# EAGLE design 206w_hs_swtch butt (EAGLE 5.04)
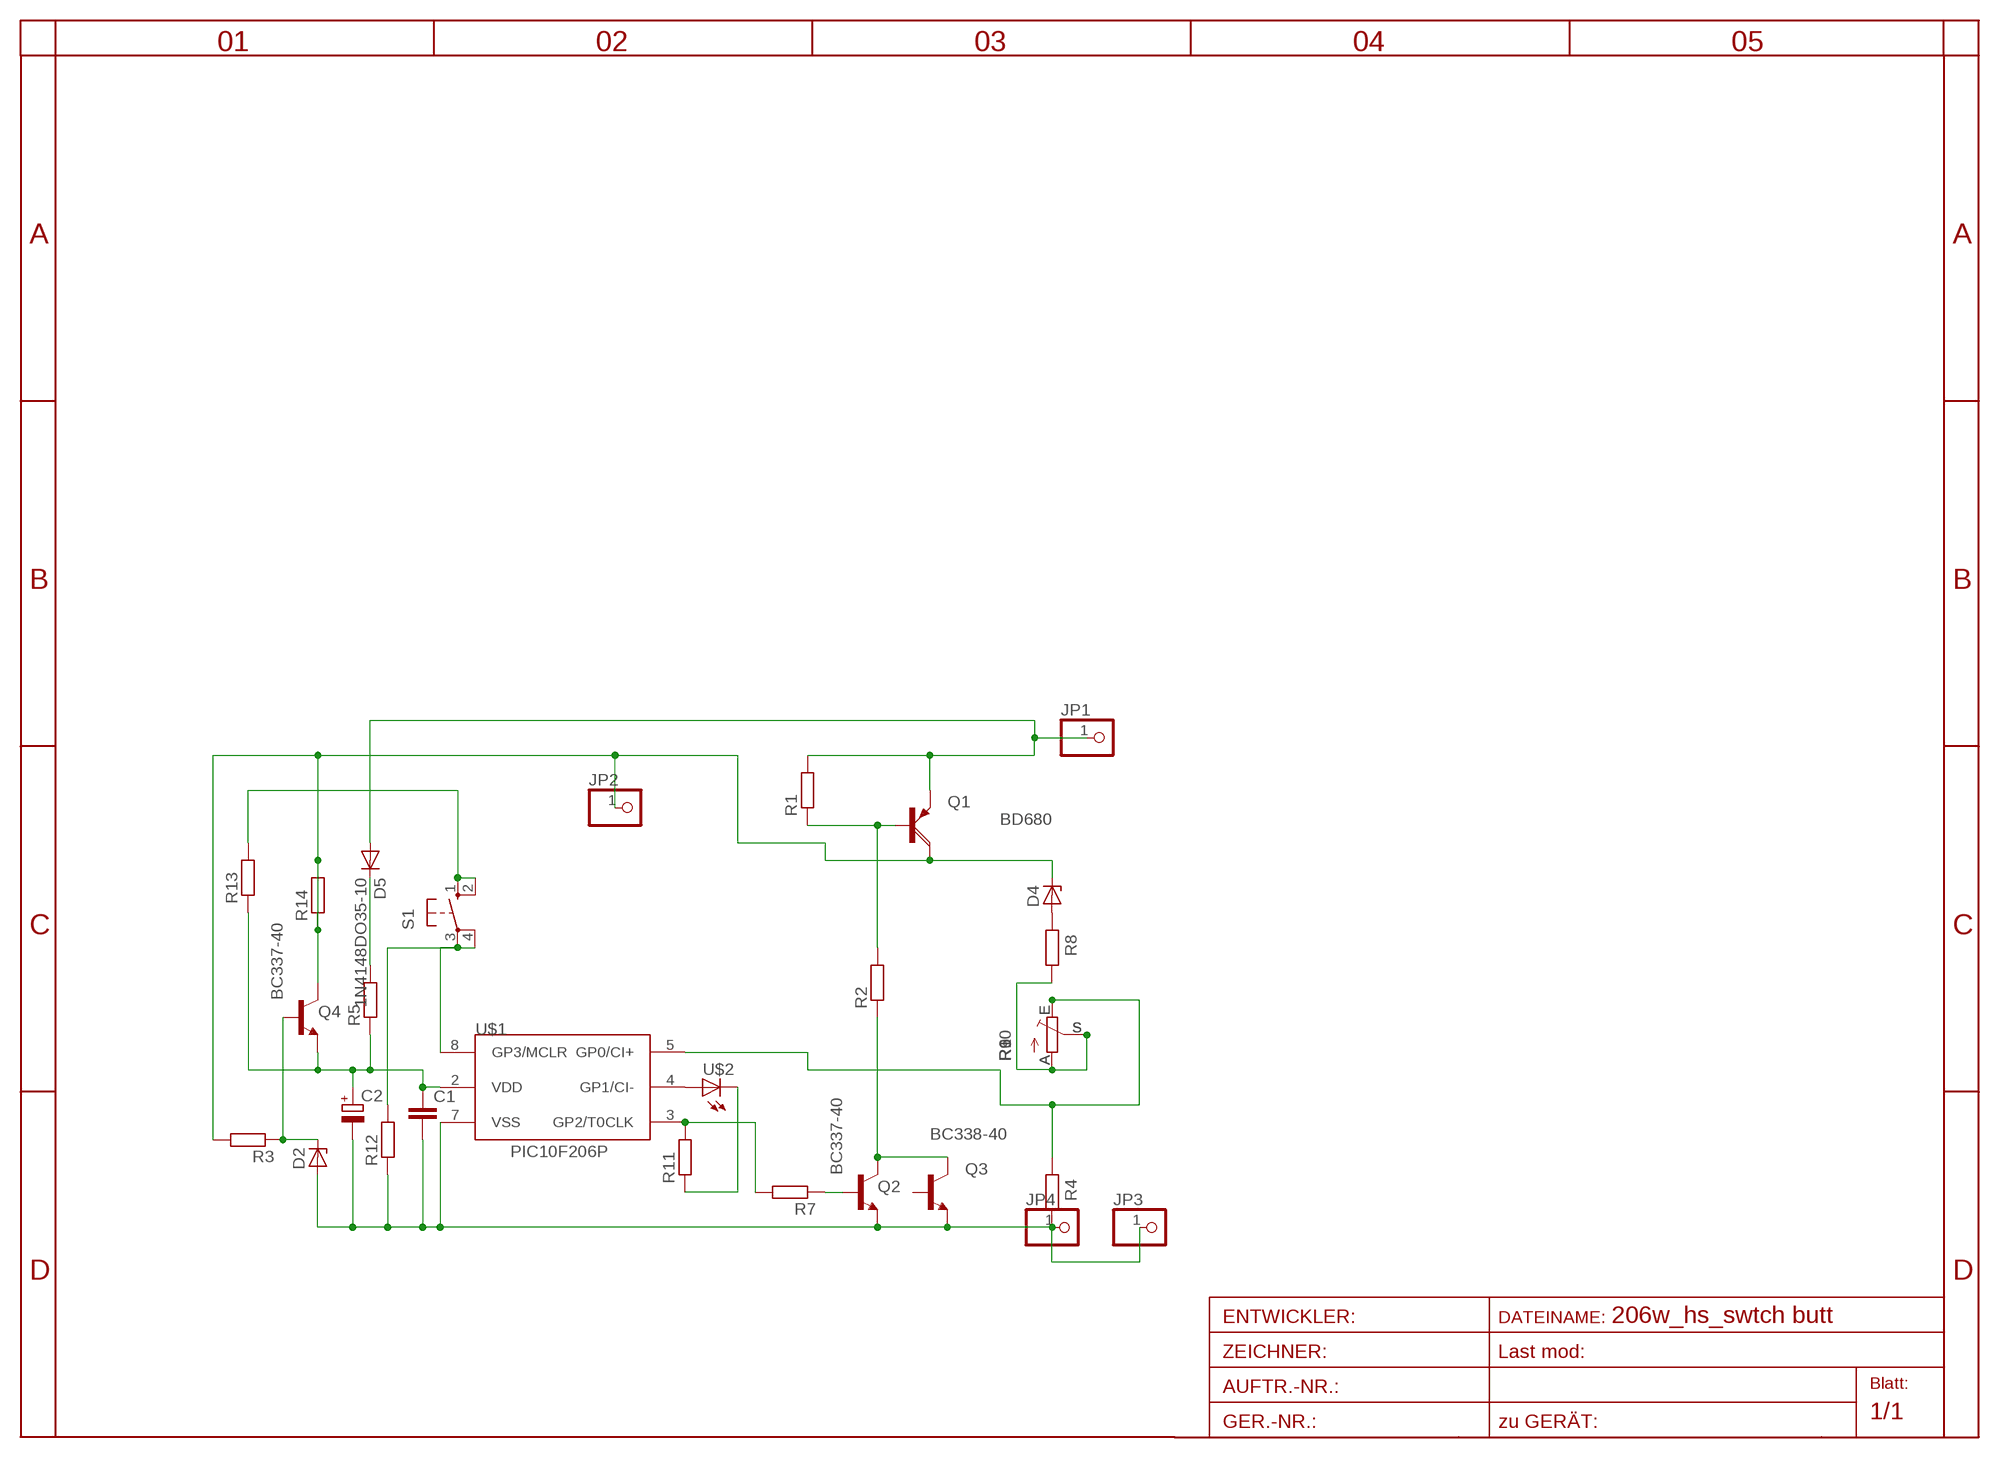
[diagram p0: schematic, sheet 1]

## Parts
C1  C-EU050-030X075  [C050-030X075]
C2  CPOL-EUE2.5-5  [E2,5-5]
D2  ZENER-DIODEZD-7.5  [ZDIO-7.5]
D4  ZENER-DIODEZD-10  [ZDIO-10]
D5  1N4148DO35-10  [DO35-10]
JP1  PINHD-1X1  [1X01]
JP2  PINHD-1X1  [1X01]
JP3  PINHD-1X1  [1X01]
JP4  PINHD-1X1  [1X01]
Q1  BD680  [TO126AV]
Q2  BC337-40  [TO92]
Q3  BC338-40  [TO92-EBC]
Q4  BC337-40  [TO92]
R1  R-EU_0207/10  [0207/10]
R2  R-EU_0207/10  [0207/10]
R3  R-EU_0207/10  [0207/10]
R4  R-EU_0207/10  [0207/10]
R5  R-EU_0207/10  [0207/10]
R6  TRIM_EU-CA6V  [CA6V]
R7  R-EU_0207/10  [0207/10]
R8  R-EU_0207/10  [0207/10]
R9  TRIM_EU-CA9V  [CA9V]
R10  TRIM_EU-LI15  [LI15]
R11  R-EU_0207/10  [0207/10]
R12  R-EU_0207/10  [0207/10]
R13  R-EU_0207/10  [0207/10]
R14  R-EU_0207/10  [0207/10]
S1  10-XX  [B3F-10XX]
U$1  PIC10F206P  [DIL8]
U$2  LED3MM  [LED3MM]

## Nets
GND: C1.2 C2.- D2.A JP3.1 JP4.1 Q2.1(E) Q3.E R4.1 R12.1 U$1.7(VSS)
N$1: D4.A R8.2
N$2: C1.1 C2.+ Q4.1(E) R5.1 R13.1 U$1.2(VDD)
N$4: D5.C R5.2
N$5: U$1.4(GP1/CI-) U$2.A
N$6: R11.1 U$2.K(C)
N$7: R4.2 R6.E R9.E R10.E U$1.5(GP0/CI+)
N$8: R6.A R6.S R8.1 R9.A R9.S R10.A R10.S
N$9: R7.2 R11.2 U$1.3(GP2/T0CLK)
N$10: Q2.2(B) R7.1
N$11: R12.2 S1.3(P) S1.4(P1) U$1.8(GP3/MCLR)
N$12: Q2.3(C) Q3.C R2.1
N$13: Q1.B R1.1 R2.2
N$15: R13.2 S1.1(S) S1.2(S1)
N$16: D2.C Q4.2(B) R3.1
N$17: D5.A JP1.1 Q1.E R1.2
V60: D4.C JP2.1 Q1.C Q4.3(C) R3.2 R14.1 R14.2
Unconnected: Q3.B

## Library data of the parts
C1 = rcl:C-EU: CAPACITOR, European symbol
C2 = rcl:CPOL-EU: POLARIZED CAPACITOR, European symbol
D2 D4 = diode-1:ZENER-DIODE: Z-Diode
D5 = diode-1:1N4148: DIODE
JP1-JP4 = pinhead:PINHD-1X1: PIN HEADER
Q1 = transistor-power:BD680: PNP DARLINGTON TRANSISTOR
Q2 Q4 = transistor-npn:BC337*: NPN Transistor
Q3 = transistor-npn:BC338*: NPN Transistor
R1-R5 R7 R8 R11-R14 = rcl:R-EU_: RESISTOR, European symbol
R6 R9 R10 = pot:TRIM_EU-: POTENTIOMETER
S1 = switch-omron:10-XX: OMRON SWITCH
U$1 = microchip-5:PIC10F2*: uPC nW 0,25/0,5k Program Flash memory Comparator
U$2 = led(2):LED: LED

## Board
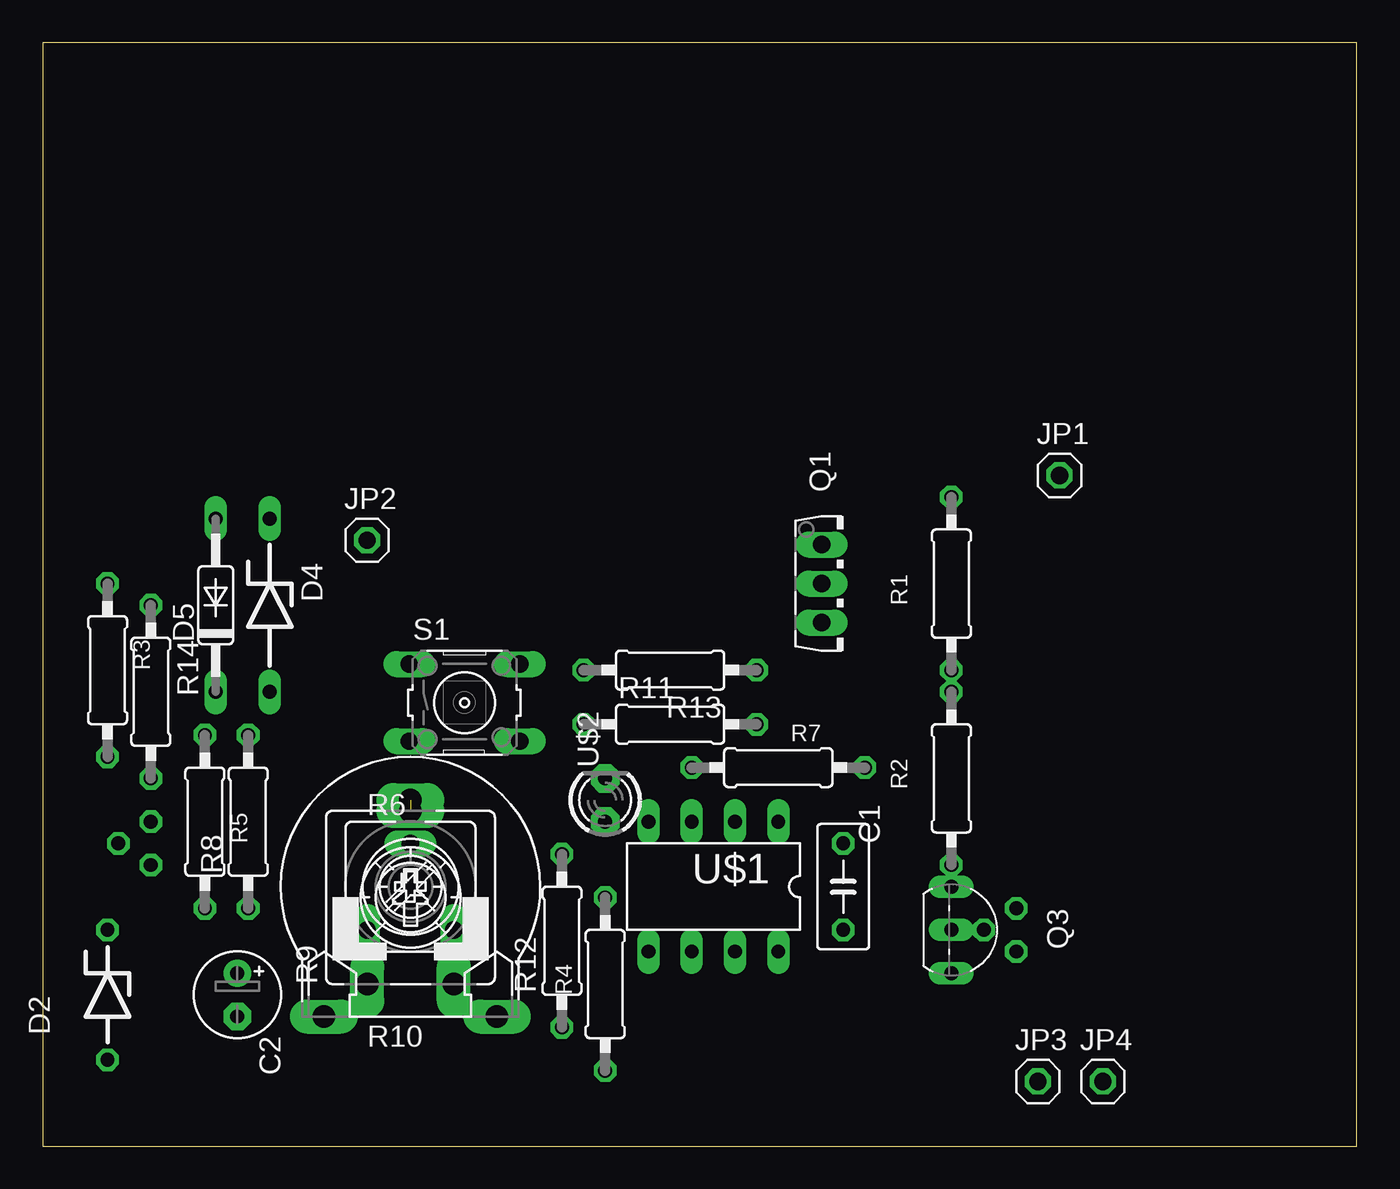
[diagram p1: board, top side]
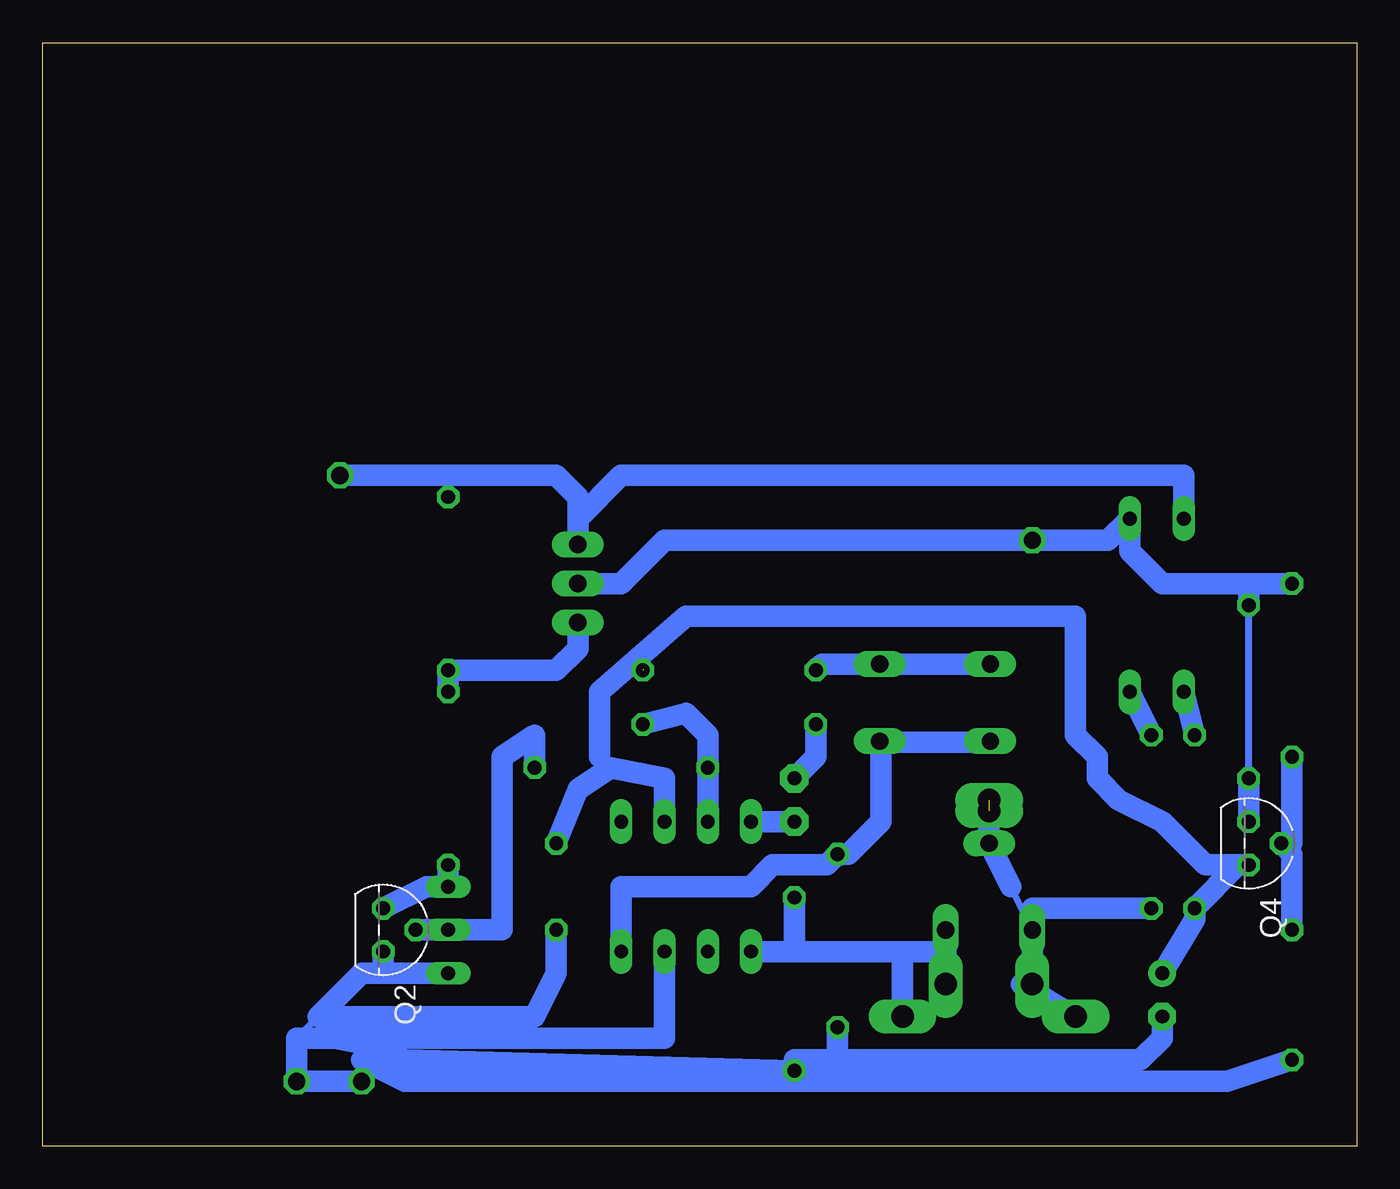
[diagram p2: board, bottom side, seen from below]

Size 77.14 x 64.76 mm. Coordinates in mm from the lower left corner, seen from the top.
Outline: 0,0 77.14,0 77.14,64.76 0,64.76 0,0
Copper layers (1*16): Top 0.035mm / dielectric 1.5mm / Bottom 0.035mm
Design rules "default": minimum track width 10mil, minimum drill 24mil, track to track 8mil, track to pad 8mil, pad to pad 8mil, via to via 8mil, smd to smd 8mil, copper to edge 40mil, drill to drill 8mil, minimum pad ring 10mil, minimum via ring 8mil, stop-mask expansion 4mil, vias tented up to drill 0mil, thermal gap 10mil

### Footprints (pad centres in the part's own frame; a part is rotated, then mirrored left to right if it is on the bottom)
C050-030X075 = drill 0.813 octagon: 1 -2.54,0; 2 2.54,0
E2,5-5 = drill 0.813 pad 1.6 round: + -1.27,0 | drill 0.813 pad 1.6 octagon: - 1.27,0
ZDIO-7.5 = drill 0.813 octagon: A 3.81,0; C -3.81,0
ZDIO-10 = drill 0.813 long: A 5.08,0; C -5.08,0
DO35-10 = drill 0.813 long: A 5.08,0; C -5.08,0
1X01 = drill 1.016 octagon: 1 0,0
TO126AV = drill 1.016 long: B 2.286,-1.27; C 0,-1.27; E -2.286,-1.27
TO92 = drill 0.813 octagon: 1 1.27,0; 2 0,1.905; 3 -1.27,0
TO92-EBC = drill 0.813 long: B 0,-1.27; C -2.54,-1.27; E 2.54,-1.27
0207/10 = drill 0.813 octagon: 1 -5.08,0; 2 5.08,0
CA6V = drill 1.016 long: A -2.54,-2.54; E 2.54,-2.54; S 0,2.54
CA9V = drill 1.321 long: A -2.54,-5.08; E 2.54,-5.08; S 0,5.08
LI15 = drill 1.321 long: A -5.08,-7.62; E 5.08,-7.62; S 0,5.08
B3F-10XX = drill 1.016 long: 1 -3.251,2.261; 2 3.251,2.261; 3 -3.251,-2.261; 4 3.251,-2.261
DIL8 = drill 0.813 long: 1 -3.81,-3.81; 2 -1.27,-3.81; 3 1.27,-3.81; 4 3.81,-3.81; 5 3.81,3.81; 6 1.27,3.81; 7 -1.27,3.81; 8 -3.81,3.81
LED3MM = drill 0.813 pad 1.676 octagon: A -1.27,0; K 1.27,0

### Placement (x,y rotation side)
C1  46.99,15.24 270 top
C2  11.43,8.89 270 top
D2  3.81,8.89 270 top
D4  13.34,31.75 270 top
D5  10.16,31.75 90 top
JP1  59.69,39.37 0 top
JP2  19.05,35.56 0 top
JP3  58.42,3.81 0 top
JP4  62.23,3.81 0 top
Q1  46.99,33.02 270 top
Q2  57.15,12.7 270 bottom
Q3  54.61,12.7 270 top
Q4  6.35,17.78 270 bottom
R1  53.34,33.02 90 top
R2  53.34,21.59 90 top
R3  3.81,27.94 90 top
R4  33.02,9.53 90 top
R5  9.53,19.05 90 top
R6  21.59,15.24 0 top
R7  43.18,22.23 180 top
R8  12.06,19.05 90 top
R9  21.59,14.61 0 top
R10  21.59,15.24 0 top
R11  36.83,24.77 0 top
R12  30.48,12.06 90 top
R13  36.83,27.94 180 top
R14  6.35,26.67 270 top
S1  24.77,26.04 0 top
U$1  39.37,15.24 180 top
U$2  33.02,20.32 90 top

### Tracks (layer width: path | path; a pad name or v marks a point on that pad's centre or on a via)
GND
  Bottom 0.406: 55.88,5.08 62.23,6.35 60.96,7.62
  Bottom 1.27: D2.A 7.62,3.81 55.88,3.81 58.42,5.08 55.88,5.08 R4.1 33.02,5.08 30.48,5.08 | 57.15,10.16 Q2.1 | C2.- 11.43,6.35 12.7,5.08 30.48,5.08 | U$1.7 40.64,6.35 62.23,6.35 JP4.1 JP3.1 | C1.2 46.99,10.16 48.26,7.62 60.96,7.62 58.42,10.16 57.15,10.16 | 57.15,10.16 Q3.E | 30.48,5.08 R12.1
N$1
  Bottom 1.27: R8.2 D4.A
N$2  (1 unrouted)
  Bottom 0.406: 44.45,22.86 43.81,22.23
  Bottom 1.27: C2.+ 9.53,13.34 R5.1 6.99,16.51 Q4.1 8.89,16.51 11.43,19.05 13.97,20.32 15.24,21.59 15.24,22.86 16.51,24.13 16.51,31.11 39.37,31.11 42.38,28.48 | 42.38,28.48 44.45,26.67 44.45,22.86 | U$1.2 40.64,21.59 43.81,22.23 45.72,20.95 C1.1 | 42.38,28.48 41.91,28.01
N$4
  Bottom 1.27: R5.2 D5.C
N$5
  Bottom 1.27: U$2.A U$1.4
N$6
  Bottom 1.27: U$2.K 31.75,22.86 R11.1
N$7
  Bottom 1.27: 26.67,11.43 R10.E | 26.67,11.43 33.02,11.43 | 33.02,11.43 U$1.5 | 33.02,11.43 R4.2 | R9.E 24.13,11.43 | 24.13,11.43 R6.E | 24.13,11.43 26.67,11.43
N$8  (1 unrouted)
  Bottom 0.406: R6.A 20.32,15.24
  Bottom 1.27: R8.1 19.05,13.97 R6.A R9.A 19.68,9.53 R10.A | R10.S R6.S 20.32,15.24
N$9
  Bottom 1.27: U$1.3 R7.2 38.1,24.13 39.37,25.4 R11.2
N$10
  Bottom 1.27: R7.1 48.26,24.13 50.16,22.86 50.16,12.7 Q2.2
N$11
  Bottom 1.27: 27.94,23.7 27.94,19.05 29.84,17.14 R12.2 31.11,16.51 34.29,16.51 35.56,15.24 43.18,15.24 U$1.8 | 27.94,23.7 S1.4 | 27.94,23.7 21.59,23.7 S1.3
N$12
  Bottom 1.27: Q2.3 54.61,15.24 Q3.C R2.1
N$13
  Bottom 1.27: Q1.B 45.72,29.21 46.99,27.94 R1.1 R2.2
N$15
  Bottom 1.27: S1.1 S1.2 31.39,28.3 R13.2
N$16
  Bottom 1.27: D2.C 3.81,17.14 Q4.2 3.81,17.78 R3.1
N$17
  Bottom 0.406: 45.72,36.83 Q1.E | 53.34,39.37 R1.2
  Bottom 1.27: D5.A 10.16,39.37 43.18,39.37 45.72,36.83 | Q1.E 45.72,38.1 46.99,39.37 53.34,39.37 JP1.1
V60
  Bottom 0.406: Q4.3 R14.2 R14.1
  Bottom 1.27: 6.35,33.02 R3.2 | Q1.C 43.18,33.02 40.64,35.56 JP2.1 14.61,35.56 D4.C 13.34,34.92 11.43,33.02 6.35,33.02 | R14.1 6.35,33.02 | R14.2 Q4.3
